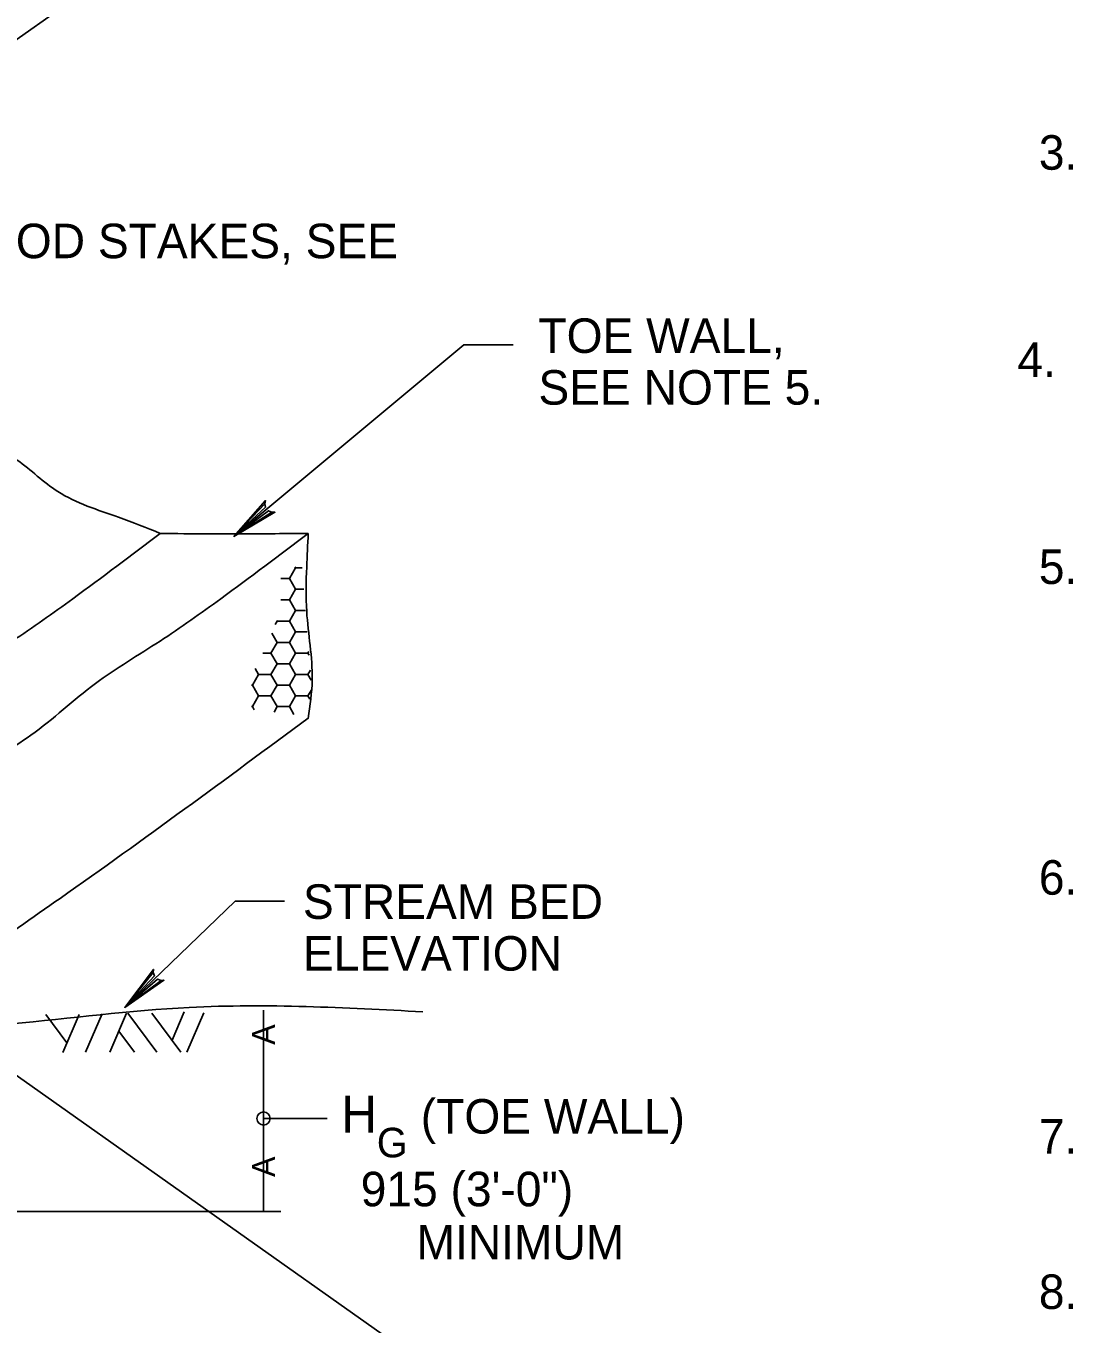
# Model space of a CAD drawing. Extents: x 3 to 3592, y -602 to 1171.
# Drawn here: x 3183.7 to 3291.2, y -382.5 to -250.9 of the extents above; entities that cross this region are included whole.
import ezdxf

# ---------------------------------------------------------------- set-up
doc = ezdxf.new("R2010")
doc.units = 0
for name, color, linetype in [('1', 7, 'Continuous'), ('2', 7, 'Continuous'), ('3', 7, 'Continuous')]:
    doc.layers.add(name, color=color, linetype=linetype)

msp = doc.modelspace()

# ---------------------------------------------------------------- linework, layer by layer
at = {"layer": '1'}
for p, q in [((2687.88, -7.81), (3528.88, -601.81)), ((2687.88, -601.81), (3528.88, -7.81))]:
    msp.add_line(p, q, dxfattribs=at)
at = {"layer": '2'}
for p, q in [((3197.33, -302.36), (3197.33, -302.36)), ((3185.71, -351.12), (3187.86, -354.01)), ((3189.11, -351.12), (3187.45, -354.98)), ((3191.42, -351.07), (3189.74, -354.97)), ((3193.91, -351.01), (3192.21, -354.97)), ((3194.04, -351.01), (3196.99, -354.95)), ((3196.47, -351), (3199.41, -354.94)), ((3199.74, -350.88), (3198.52, -353.74)), ((3201.73, -350.98), (3200.02, -354.94)), ((3207.8, -371.11), (3207.8, -350.71)), ((3193.13, -352.83), (3194.72, -354.96)), ((3144.08, -371.11), (3209.55, -371.11))]:
    msp.add_line(p, q, dxfattribs=at)
for points in [[(3233.12, -283.25), (3228.12, -283.25), (3204.79, -302.67)], [(3208.65, -300.2), (3208.31, -300.06), (3204.79, -302.67), (3208.65, -300.2), (3208.95, -300.21), (3204.79, -302.67), (3208.01, -299.71), (3207.93, -299.36), (3204.79, -302.67), (3207.98, -299.03), (3207.93, -299.36)], [(3211.05, -305.85), (3210.43, -306.93)], [(3210.43, -306.93), (3211.05, -305.85)], [(3211, -305.75), (3211.05, -305.85)], [(3211.05, -305.85), (3211, -305.75)], [(3211.05, -305.85), (3211.7, -305.85)], [(3211.7, -305.85), (3211.05, -305.85)], [(3210.43, -306.93), (3209.55, -306.93)], [(3209.55, -306.93), (3210.43, -306.93)], [(3211.05, -308.01), (3210.43, -306.93)], [(3210.43, -306.93), (3211.05, -308.01)], [(3209.55, -309.1), (3210.43, -309.1), (3211.05, -310.18), (3210.43, -311.26), (3209.18, -311.26), (3209.14, -311.2)], [(3210.43, -309.1), (3209.55, -309.1)], [(3211.05, -308.01), (3210.43, -309.1)], [(3210.43, -309.1), (3211.05, -308.01)], [(3211.05, -310.18), (3210.43, -309.1)], [(3211.87, -308.01), (3211.05, -308.01)], [(3211.05, -308.01), (3211.87, -308.01)], [(3210.43, -311.26), (3211.05, -310.18)], [(3212.05, -310.18), (3211.05, -310.18)], [(3211.05, -310.18), (3212.05, -310.18)], [(3208.98, -311.6), (3209.18, -311.26), (3210.43, -311.26), (3211.05, -312.34), (3210.43, -313.43), (3209.18, -313.43), (3208.63, -312.48)], [(3209.14, -311.2), (3209.18, -311.26), (3208.98, -311.6)], [(3211.05, -312.34), (3210.43, -311.26)], [(3212.23, -312.34), (3211.05, -312.34)], [(3207.74, -314.51), (3208.55, -314.51), (3209.18, -315.59), (3208.55, -316.67), (3207.3, -316.67), (3206.95, -316.07)], [(3210.43, -315.59), (3211.05, -314.51)], [(3211.05, -314.51), (3212.3, -314.51)], [(3212.3, -314.51), (3212.4, -314.35)], [(3212.3, -314.51), (3212.43, -314.72)], [(3212.43, -314.72), (3212.3, -314.51)], [(3211.05, -316.67), (3210.43, -315.59)], [(3206.95, -316.07), (3207.3, -316.67), (3206.68, -317.76), (3206.57, -317.76)], [(3210.43, -317.76), (3211.05, -316.67)], [(3211.05, -316.67), (3212.3, -316.67)], [(3212.3, -316.67), (3211.05, -316.67)], [(3212.55, -316.24), (3212.3, -316.67)], [(3212.3, -316.67), (3212.55, -316.24)], [(3212.3, -316.67), (3212.63, -317.25)], [(3212.63, -317.25), (3212.3, -316.67)], [(3206.57, -317.76), (3206.68, -317.76), (3207.3, -318.84), (3206.68, -319.92), (3206.57, -319.92)], [(3211.05, -318.84), (3210.43, -317.76)], [(3212.68, -318.19), (3212.3, -318.84)], [(3212.3, -318.84), (3212.68, -318.19)], [(3206.68, -319.92), (3207.3, -318.84)], [(3207.3, -318.84), (3208.55, -318.84)], [(3208.55, -318.84), (3209.18, -319.92)], [(3210.43, -319.92), (3211.05, -318.84)], [(3212.3, -318.84), (3211.05, -318.84)], [(3211.05, -318.84), (3212.3, -318.84)], [(3212.49, -319.17), (3212.3, -318.84)], [(3212.3, -318.84), (3212.49, -319.17)], [(3206.57, -319.92), (3206.68, -319.92)], [(3206.86, -320.24), (3206.68, -319.92)], [(3206.68, -319.92), (3206.86, -320.24)], [(3209.18, -319.92), (3208.86, -320.47)], [(3208.86, -320.47), (3209.18, -319.92)], [(3209.18, -319.92), (3210.43, -319.92)], [(3210.88, -320.71), (3210.43, -319.92)], [(3210.43, -319.92), (3210.88, -320.71)], [(3209.92, -339.63), (3204.92, -339.63), (3193.73, -350.42)], [(3197.4, -347.68), (3197.05, -347.56), (3193.73, -350.42), (3197.4, -347.68), (3197.7, -347.66), (3193.73, -350.42), (3196.73, -347.23), (3196.61, -346.89), (3193.73, -350.42), (3196.64, -346.56), (3196.61, -346.89)], [(3214.25, -361.68), (3207.8, -361.68)]]:
    msp.add_lwpolyline(points, dxfattribs=at)
for points in [[(3208.55, -314.51), (3209.18, -313.43), (3210.43, -313.43), (3211.05, -314.51), (3210.43, -315.59), (3209.18, -315.59)], [(3208.55, -316.67), (3209.18, -315.59), (3210.43, -315.59), (3211.05, -316.67), (3210.43, -317.76), (3209.18, -317.76)], [(3206.68, -317.76), (3207.3, -316.67), (3208.55, -316.67), (3209.18, -317.76), (3208.55, -318.84), (3207.3, -318.84)], [(3208.55, -318.84), (3209.18, -317.76), (3210.43, -317.76), (3211.05, -318.84), (3210.43, -319.92), (3209.18, -319.92)]]:
    msp.add_lwpolyline(points, close=True, dxfattribs=at)
msp.add_circle((3207.8, -361.68), 0.668, dxfattribs=at)
for points in [[(3134.83, -271.11), (3143.36, -275.11), (3151.4, -279.41), (3156.26, -281.85), (3161.69, -284.65), (3168.42, -288.2), (3175.9, -291.57), (3182.81, -294.93), (3186.93, -298.11), (3193.1, -300.73), (3197.33, -302.36)], [(3127.33, -352.36), (3132.19, -348.25), (3136.3, -346), (3142.66, -340.96), (3146.21, -338.34), (3152.38, -335.53), (3155.38, -332.73), (3158.18, -329.74), (3163.04, -326.56), (3169.21, -322.82), (3175.76, -317.58), (3182.3, -313.28), (3188.47, -308.98), (3197.33, -302.36)], [(3142.33, -352.36), (3147.19, -348.25), (3151.3, -346), (3157.66, -340.96), (3161.21, -338.34), (3167.38, -335.53), (3170.38, -332.73), (3173.18, -329.74), (3178.04, -326.56), (3184.21, -322.82), (3190.76, -317.58), (3197.3, -313.28), (3203.47, -308.98), (3212.33, -302.36)], [(3197.33, -302.36), (3202.07, -302.41), (3205.63, -302.41), (3212.33, -302.36)], [(3212.33, -302.36), (3212.17, -305.78), (3212.17, -310.27), (3212.73, -317.19), (3212.33, -321.11)], [(3212.33, -321.09), (3187.17, -339.36), (3170.29, -351.15), (3154.44, -362.65), (3142.33, -371.09)], [(3142.33, -352.36), (3148.6, -352.71), (3154.95, -351.96), (3164.12, -352.52), (3200.26, -350.42), (3223.96, -350.86)]]:
    msp.add_spline(points, degree=3, dxfattribs=at)

# ---------------------------------------------------------------- texts
for p in [(3208.96, -354.21), (3208.96, -367.61)]:
    msp.add_text('A', height=2.33, rotation=90, dxfattribs=at).set_placement(p)
at = {"layer": '3'}
for s, height, p in [('3.  ', 3.5, (3286.41, -265.49)), ('HARDWOOD STAKES, SEE', 3.5, (3161.36, -274.46)), ('TOE WALL,', 3.5, (3235.67, -284.06)), (' 4.  ', 3.5, (3282.94, -286.49)), ('SEE NOTE 5.', 3.5, (3235.67, -289.31)), ('5.  ', 3.5, (3286.41, -307.49)), ('6.  ', 3.5, (3286.41, -338.99)), ('STREAM BED', 3.5, (3211.79, -341.44)), ('ELEVATION', 3.5, (3211.79, -346.69)), ('H', 3.75, (3215.69, -363.1)), ('(TOE WALL)', 3.5, (3223.74, -363.21)), ('7.  ', 3.5, (3286.41, -365.24)), ('G', 3, (3219.28, -365.62)), ('915 (3\'-0")', 3.5, (3217.65, -370.58)), ('MINIMUM', 3.5, (3223.31, -375.97)), ('8.  ', 3.5, (3286.41, -380.99))]:
    msp.add_text(s, height=height, dxfattribs=at).set_placement(p)

doc.saveas('drawing.dxf')
